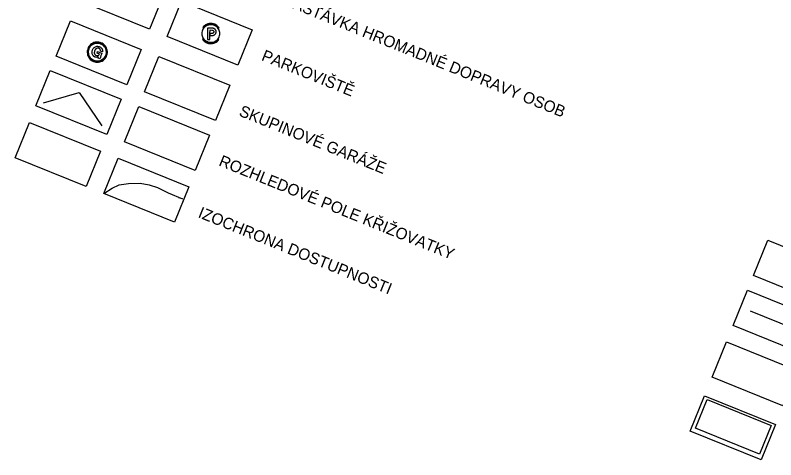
# Model space of a CAD drawing. Extents: x -522754 to -518969, y -1191121 to -1188171.
# Drawn here: x -521907 to -520911, y -1190701 to -1190119 of the extents above; entities that cross this region are included whole.
import ezdxf

# ---------------------------------------------------------------- set-up
doc = ezdxf.new("R2010")
doc.units = 0
for name, color, linetype in [('Implicitní', 7, 'Continuous'), ('ložisk_nerost', 7, 'Continuous'), ('odvodneni_s', 7, 'Continuous'), ('pe_prikop_s', 7, 'Continuous'), ('rozhled_pole_s', 7, 'Continuous')]:
    doc.layers.add(name, color=color, linetype=linetype)

msp = doc.modelspace()

# ---------------------------------------------------------------- linework, layer by layer
at = {"layer": 'Implicitní'}
for points in [[(-521804.94, -1190053.63), (-521712.26, -1190091.19), (-521731.04, -1190137.53), (-521823.72, -1190099.97)], [(-521689.09, -1190100.58), (-521596.41, -1190138.15), (-521615.19, -1190184.48), (-521707.87, -1190146.92)], [(-521834.39, -1190126.29), (-521741.71, -1190163.85), (-521760.49, -1190210.19), (-521853.17, -1190172.63)], [(-521718.54, -1190173.25), (-521625.86, -1190210.81), (-521644.64, -1190257.15), (-521737.32, -1190219.58)], [(-521860.85, -1190191.58), (-521768.17, -1190229.14), (-521786.95, -1190275.48), (-521879.63, -1190237.92)], [(-521745, -1190238.53), (-521652.32, -1190276.1), (-521671.1, -1190322.43), (-521763.78, -1190284.87)], [(-521887.96, -1190259.38), (-521795.28, -1190296.92), (-521814.05, -1190343.26), (-521906.73, -1190305.72)], [(-521772.11, -1190306.3), (-521679.42, -1190343.85), (-521698.19, -1190390.19), (-521790.88, -1190352.65)], [(-520921.74, -1190413.62), (-520829.06, -1190451.18), (-520847.84, -1190497.52), (-520940.52, -1190459.96)], [(-520948.23, -1190478.99), (-520855.55, -1190516.55), (-520874.33, -1190562.89), (-520967.01, -1190525.33)], [(-520975.71, -1190546.78), (-520883.03, -1190584.34), (-520901.81, -1190630.68), (-520994.49, -1190593.12)], [(-521004.31, -1190617.35), (-520911.63, -1190654.91), (-520930.41, -1190701.25), (-521023.09, -1190663.69)]]:
    msp.add_lwpolyline(points, close=True, dxfattribs=at)
msp.add_lwpolyline([(-521869.54, -1190233.73), (-521823.19, -1190220.35), (-521793.32, -1190263.89)], dxfattribs=at)
at = {"layer": 'ložisk_nerost'}
for points in [[(-521638.84, -1190143.37), (-521638.9, -1190141.86), (-521639.15, -1190140.38), (-521639.59, -1190138.95), (-521640.2, -1190137.57), (-521640.98, -1190136.29), (-521641.92, -1190135.12), (-521643, -1190134.07), (-521644.2, -1190133.17), (-521645.51, -1190132.42), (-521646.9, -1190131.85), (-521648.35, -1190131.46), (-521649.84, -1190131.25), (-521651.34, -1190131.24), (-521652.83, -1190131.41), (-521654.29, -1190131.77), (-521655.7, -1190132.31), (-521657.02, -1190133.03), (-521658.24, -1190133.9), (-521659.34, -1190134.92), (-521660.31, -1190136.08), (-521661.12, -1190137.34), (-521661.76, -1190138.7), (-521662.23, -1190140.13), (-521662.51, -1190141.6), (-521662.61, -1190143.1), (-521662.52, -1190144.6), (-521662.23, -1190146.08), (-521661.77, -1190147.51), (-521661.12, -1190148.87), (-521660.31, -1190150.13), (-521659.35, -1190151.29), (-521658.25, -1190152.31), (-521657.03, -1190153.19), (-521655.71, -1190153.9), (-521654.3, -1190154.45), (-521652.85, -1190154.81), (-521651.35, -1190154.98), (-521649.85, -1190154.97), (-521648.36, -1190154.76), (-521646.91, -1190154.37), (-521645.52, -1190153.8), (-521644.21, -1190153.06), (-521643.01, -1190152.16), (-521641.93, -1190151.11), (-521640.99, -1190149.94), (-521640.21, -1190148.65), (-521639.59, -1190147.28), (-521639.15, -1190145.85), (-521638.9, -1190144.36), (-521638.84, -1190143.37)], [(-521650.45, -1190129.9), (-521651.28, -1190129.91), (-521652.94, -1190130.09), (-521654.56, -1190130.47), (-521656.13, -1190131.05), (-521657.61, -1190131.83), (-521658.97, -1190132.79), (-521660.21, -1190133.91), (-521661.29, -1190135.18)], [(-521659.62, -1190135.21), (-521658.73, -1190134.31), (-521657.56, -1190133.37), (-521656.27, -1190132.59), (-521654.9, -1190131.98), (-521653.46, -1190131.54), (-521651.98, -1190131.29), (-521650.48, -1190131.22)], [(-521650.47, -1190131.22), (-521649.21, -1190131.32), (-521647.73, -1190131.61), (-521646.3, -1190132.08), (-521644.95, -1190132.72), (-521643.68, -1190133.54), (-521642.53, -1190134.5), (-521641.51, -1190135.61)], [(-521639.84, -1190135.64), (-521640.32, -1190134.98), (-521641.43, -1190133.73), (-521642.69, -1190132.63), (-521644.08, -1190131.7), (-521645.57, -1190130.95), (-521647.14, -1190130.4), (-521648.78, -1190130.05), (-521650.44, -1190129.9)], [(-521661.29, -1190135.18), (-521659.62, -1190135.21)], [(-521648.4, -1190136.03), (-521654.85, -1190135.89), (-521655.17, -1190150.78), (-521652, -1190150.85), (-521651.83, -1190142.99)], [(-521651.78, -1190142.99), (-521651.84, -1190145.57)], [(-521651.83, -1190142.99), (-521651.73, -1190138.42)], [(-521649.25, -1190143.05), (-521651.78, -1190142.99)], [(-521651.73, -1190138.42), (-521649.16, -1190138.48)], [(-521649.16, -1190138.48), (-521649.04, -1190138.48), (-521648.92, -1190138.48), (-521648.34, -1190138.61), (-521648.11, -1190138.74), (-521647.87, -1190138.86), (-521647.64, -1190138.98), (-521647.41, -1190139.22), (-521647.18, -1190139.46), (-521646.96, -1190139.81), (-521646.85, -1190140.17), (-521646.74, -1190140.76), (-521646.75, -1190140.99), (-521646.87, -1190141.46), (-521647, -1190141.81), (-521647.24, -1190142.15), (-521647.36, -1190142.27), (-521647.6, -1190142.5), (-521647.96, -1190142.73), (-521648.19, -1190142.84), (-521648.55, -1190142.95), (-521649.02, -1190143.05), (-521649.25, -1190143.05)], [(-521648.61, -1190145.64), (-521647.9, -1190145.54), (-521647.43, -1190145.43), (-521647.08, -1190145.33), (-521646.72, -1190145.21), (-521646.48, -1190145.1), (-521646.25, -1190144.99), (-521645.89, -1190144.76), (-521645.53, -1190144.54), (-521645.29, -1190144.31), (-521645.05, -1190144.08), (-521644.81, -1190143.85), (-521644.57, -1190143.5), (-521644.33, -1190143.16), (-521644.21, -1190142.92), (-521644.09, -1190142.69), (-521643.96, -1190142.34), (-521643.84, -1190141.99), (-521643.71, -1190141.41), (-521643.7, -1190141.06), (-521643.69, -1190140.59), (-521643.79, -1190140), (-521643.79, -1190139.88), (-521643.9, -1190139.53), (-521644.01, -1190139.18), (-521644.24, -1190138.7), (-521644.46, -1190138.35), (-521644.69, -1190137.99), (-521644.92, -1190137.75), (-521645.15, -1190137.51), (-521645.38, -1190137.27), (-521645.72, -1190137.03), (-521646.07, -1190136.79), (-521646.3, -1190136.66), (-521646.53, -1190136.54), (-521646.88, -1190136.42), (-521647.11, -1190136.29), (-521647.7, -1190136.16), (-521648.4, -1190136.03)], [(-521641.51, -1190135.61), (-521639.84, -1190135.64)], [(-521661.63, -1190150.57), (-521660.61, -1190151.88), (-521659.42, -1190153.06), (-521658.1, -1190154.07), (-521656.65, -1190154.92), (-521655.12, -1190155.57), (-521653.51, -1190156.02), (-521651.86, -1190156.27), (-521650.19, -1190156.31), (-521648.53, -1190156.13), (-521646.9, -1190155.75), (-521645.34, -1190155.17), (-521643.86, -1190154.39), (-521642.49, -1190153.43), (-521641.25, -1190152.31), (-521640.17, -1190151.04)], [(-521659.96, -1190150.61), (-521661.63, -1190150.57)], [(-521641.84, -1190151), (-521642.57, -1190151.75), (-521643.73, -1190152.71), (-521644.99, -1190153.52), (-521646.35, -1190154.16), (-521647.78, -1190154.63), (-521649.26, -1190154.91), (-521650.76, -1190155), (-521652.26, -1190154.9), (-521653.74, -1190154.61), (-521655.16, -1190154.14), (-521656.52, -1190153.49), (-521657.78, -1190152.68), (-521658.94, -1190151.71), (-521659.96, -1190150.61)], [(-521651.84, -1190145.57), (-521648.61, -1190145.64)], [(-521640.17, -1190151.04), (-521641.84, -1190151)], [(-521790.88, -1190352.65), (-521779.84, -1190345.61), (-521770.73, -1190341.03), (-521758.3, -1190339.3), (-521743.12, -1190339.05), (-521731.4, -1190341.17), (-521720.65, -1190344.53), (-521706.42, -1190351.6), (-521687.85, -1190359.41), (-521692.54, -1190358.08)]]:
    msp.add_lwpolyline(points, dxfattribs=at)
at = {"layer": 'odvodneni_s'}
msp.add_lwpolyline([(-521001.1, -1190622.49), (-520917.22, -1190656.49), (-520932.43, -1190694.02), (-521016.31, -1190660.03)], close=True, dxfattribs=at)
at = {"layer": 'pe_prikop_s'}
msp.add_line((-520944.8, -1190506.25), (-520870.66, -1190536.3), dxfattribs=at)
at = {"layer": 'rozhled_pole_s'}
for points in [[(-521794.49, -1190155.1), (-521795.53, -1190154.74), (-521797.16, -1190154.38), (-521798.82, -1190154.22), (-521800.49, -1190154.27), (-521802.14, -1190154.53), (-521803.75, -1190155), (-521805.28, -1190155.66), (-521806.71, -1190156.51), (-521808.03, -1190157.54), (-521809.2, -1190158.73), (-521810.22, -1190160.05), (-521811.06, -1190161.5), (-521811.72, -1190163.03), (-521812.17, -1190164.64), (-521812.42, -1190166.29), (-521812.45, -1190167.96), (-521812.28, -1190169.62), (-521811.9, -1190171.25), (-521811.31, -1190172.81), (-521810.54, -1190174.29), (-521809.58, -1190175.66), (-521808.46, -1190176.89), (-521807.19, -1190177.98), (-521805.79, -1190178.9), (-521804.29, -1190179.63), (-521802.71, -1190180.17), (-521801.07, -1190180.5), (-521799.41, -1190180.63), (-521797.74, -1190180.54), (-521796.1, -1190180.24), (-521794.51, -1190179.74), (-521792.99, -1190179.04), (-521791.57, -1190178.16), (-521790.28, -1190177.1), (-521789.13, -1190175.89), (-521788.14, -1190174.55), (-521787.33, -1190173.09), (-521786.71, -1190171.54), (-521786.29, -1190169.92), (-521786.08, -1190168.26), (-521786.07, -1190166.59), (-521786.28, -1190164.94), (-521786.7, -1190163.32), (-521787.32, -1190161.77), (-521788.13, -1190160.31), (-521789.11, -1190158.96), (-521790.26, -1190157.75), (-521791.55, -1190156.69), (-521792.97, -1190155.8), (-521794.48, -1190155.1)], [(-521794.96, -1190156.33), (-521794.05, -1190156.73), (-521792.75, -1190157.47), (-521791.54, -1190158.37), (-521790.46, -1190159.42), (-521789.52, -1190160.59), (-521788.74, -1190161.87), (-521788.13, -1190163.24), (-521787.69, -1190164.68), (-521787.43, -1190166.16), (-521787.37, -1190167.67), (-521787.5, -1190169.16), (-521787.81, -1190170.63), (-521788.31, -1190172.05), (-521788.98, -1190173.4), (-521789.82, -1190174.64), (-521790.8, -1190175.78), (-521791.93, -1190176.78), (-521793.17, -1190177.63), (-521794.5, -1190178.31), (-521795.92, -1190178.83), (-521797.38, -1190179.16), (-521798.88, -1190179.3), (-521800.38, -1190179.25), (-521801.87, -1190179.02), (-521803.31, -1190178.59), (-521804.69, -1190177.99), (-521805.98, -1190177.22), (-521807.16, -1190176.3), (-521808.22, -1190175.23), (-521809.13, -1190174.04), (-521809.89, -1190172.74), (-521810.47, -1190171.35), (-521810.88, -1190169.91), (-521811.1, -1190168.42), (-521811.14, -1190166.92), (-521810.98, -1190165.42), (-521810.63, -1190163.96), (-521810.1, -1190162.55), (-521809.4, -1190161.22), (-521808.54, -1190159.99), (-521807.53, -1190158.88), (-521806.39, -1190157.9), (-521805.13, -1190157.08), (-521803.78, -1190156.42), (-521802.35, -1190155.94), (-521800.88, -1190155.64), (-521799.38, -1190155.53), (-521797.88, -1190155.61), (-521796.4, -1190155.88), (-521794.97, -1190156.33)], [(-521788.17, -1190171.71), (-521787.72, -1190170.28), (-521787.45, -1190168.8), (-521787.37, -1190167.3), (-521787.48, -1190165.8), (-521787.78, -1190164.32), (-521788.26, -1190162.9), (-521788.92, -1190161.55), (-521789.74, -1190160.29), (-521790.72, -1190159.15), (-521791.83, -1190158.14), (-521793.06, -1190157.27), (-521794.39, -1190156.57), (-521795.79, -1190156.04), (-521797.26, -1190155.7), (-521798.75, -1190155.54), (-521800.25, -1190155.57), (-521801.74, -1190155.79), (-521803.19, -1190156.2), (-521804.57, -1190156.78), (-521805.87, -1190157.54), (-521807.06, -1190158.45), (-521808.13, -1190159.51), (-521809.06, -1190160.69), (-521809.83, -1190161.98), (-521810.43, -1190163.36), (-521810.85, -1190164.8), (-521811.09, -1190166.29), (-521811.14, -1190167.79), (-521811, -1190169.29), (-521810.67, -1190170.75), (-521810.16, -1190172.17), (-521809.47, -1190173.5), (-521808.62, -1190174.74), (-521807.62, -1190175.87), (-521806.49, -1190176.85), (-521805.24, -1190177.69), (-521803.9, -1190178.36), (-521802.48, -1190178.86), (-521801.01, -1190179.18), (-521799.51, -1190179.3), (-521798.01, -1190179.24), (-521796.53, -1190178.99), (-521795.09, -1190178.55), (-521793.72, -1190177.94), (-521792.43, -1190177.15), (-521791.26, -1190176.21), (-521790.21, -1190175.14), (-521789.31, -1190173.93), (-521788.57, -1190172.63), (-521788.17, -1190171.71)], [(-521805.54, -1190164.41), (-521804.51, -1190162.66)], [(-521804.51, -1190162.66), (-521804.1, -1190162.23)], [(-521804.1, -1190162.23), (-521803.65, -1190161.68)], [(-521803.65, -1190161.68), (-521803.14, -1190161.29)], [(-521803.14, -1190161.29), (-521802.77, -1190160.95)], [(-521802.77, -1190160.95), (-521802.44, -1190160.72)], [(-521802.44, -1190160.72), (-521800.86, -1190160.02)], [(-521800.79, -1190162.91), (-521801.3, -1190163.31)], [(-521800.86, -1190160.02), (-521799.69, -1190159.76)], [(-521800.28, -1190162.51), (-521800.79, -1190162.91)], [(-521799.56, -1190162.2), (-521800.28, -1190162.51)], [(-521799.69, -1190159.76), (-521799.44, -1190159.74)], [(-521799.31, -1190162.17), (-521799.56, -1190162.2)], [(-521799.44, -1190159.74), (-521798.84, -1190159.73)], [(-521798.92, -1190162.09), (-521799.31, -1190162.17)], [(-521798.32, -1190162.08), (-521798.92, -1190162.09)], [(-521798.84, -1190159.73), (-521797.94, -1190159.85)], [(-521797.87, -1190162.14), (-521798.32, -1190162.08)], [(-521797.94, -1190159.85), (-521796.86, -1190160.14)], [(-521797.04, -1190162.46), (-521797.87, -1190162.14)], [(-521796.56, -1190162.76), (-521797.04, -1190162.46)], [(-521796.86, -1190160.14), (-521796.03, -1190160.47)], [(-521796.29, -1190162.99), (-521796.56, -1190162.76)], [(-521796.02, -1190163.21), (-521796.29, -1190162.99)], [(-521796.03, -1190160.47), (-521795.24, -1190160.89)], [(-521795.62, -1190163.72), (-521796.02, -1190163.21)], [(-521795.24, -1190160.89), (-521794.77, -1190161.19)], [(-521794.97, -1190156.33), (-521794.49, -1190155.1)], [(-521794.48, -1190155.1), (-521794.96, -1190156.33)], [(-521794.77, -1190161.19), (-521794.49, -1190161.42)], [(-521794.49, -1190161.42), (-521794.22, -1190161.64)], [(-521794.22, -1190161.64), (-521793.89, -1190162.01)], [(-521793.89, -1190162.01), (-521793.49, -1190162.52)], [(-521793.49, -1190162.52), (-521793.2, -1190162.99)], [(-521793.2, -1190162.99), (-521793.07, -1190163.28)], [(-521806.18, -1190168.21), (-521806.13, -1190167.16)], [(-521806.15, -1190168.46), (-521806.18, -1190168.21)], [(-521806.13, -1190168.71), (-521806.15, -1190168.46)], [(-521806.13, -1190167.16), (-521806.01, -1190166.25)], [(-521806.04, -1190169.1), (-521806.13, -1190168.71)], [(-521805.93, -1190169.73), (-521806.04, -1190169.1)], [(-521806.01, -1190166.25), (-521805.92, -1190165.69)], [(-521805.17, -1190171.46), (-521805.93, -1190169.73)], [(-521805.92, -1190165.69), (-521805.78, -1190165.03)], [(-521805.78, -1190165.03), (-521805.54, -1190164.41)], [(-521804.77, -1190171.97), (-521805.17, -1190171.46)], [(-521804.54, -1190172.3), (-521804.77, -1190171.97)], [(-521804.38, -1190172.48), (-521804.54, -1190172.3)], [(-521804.11, -1190172.7), (-521804.38, -1190172.48)], [(-521803.94, -1190172.89), (-521804.11, -1190172.7)], [(-521803.56, -1190173.15), (-521803.94, -1190172.89)], [(-521803.29, -1190173.38), (-521803.56, -1190173.15)], [(-521803.17, -1190167.83), (-521803.23, -1190168.28)], [(-521803.23, -1190168.28), (-521803.01, -1190169.56)], [(-521803.15, -1190167.48), (-521803.17, -1190167.83)], [(-521803.04, -1190166.57), (-521803.15, -1190167.48)], [(-521802.8, -1190165.95), (-521803.04, -1190166.57)], [(-521803.01, -1190169.56), (-521802.94, -1190169.7)], [(-521802.94, -1190169.7), (-521802.81, -1190169.99)], [(-521802.81, -1190169.99), (-521802.69, -1190170.28)], [(-521802.32, -1190164.7), (-521802.8, -1190165.95)], [(-521802.69, -1190170.28), (-521802.52, -1190170.46)], [(-521802.52, -1190170.46), (-521802.29, -1190170.79)], [(-521802.05, -1190164.33), (-521802.32, -1190164.7)], [(-521802.29, -1190170.79), (-521801.85, -1190171.19)], [(-521801.79, -1190163.95), (-521802.05, -1190164.33)], [(-521801.85, -1190171.19), (-521801.48, -1190171.46)], [(-521801.56, -1190163.68), (-521801.79, -1190163.95)], [(-521801.3, -1190163.31), (-521801.56, -1190163.68)], [(-521801.48, -1190171.46), (-521800.75, -1190171.74)], [(-521800.75, -1190171.74), (-521800.09, -1190171.88)], [(-521800.09, -1190171.88), (-521799.64, -1190171.93)], [(-521799.64, -1190171.93), (-521799.14, -1190171.89)], [(-521799.63, -1190168.84), (-521798.83, -1190166.77)], [(-521796.42, -1190170.08), (-521799.63, -1190168.84)], [(-521799.14, -1190171.89), (-521798.5, -1190171.77)], [(-521798.83, -1190166.77), (-521795.83, -1190167.93)], [(-521798.5, -1190171.77), (-521798.36, -1190171.71)], [(-521798.36, -1190171.71), (-521797.79, -1190171.46)], [(-521797.79, -1190171.46), (-521797.46, -1190171.23)], [(-521797.46, -1190171.23), (-521796.91, -1190170.73)], [(-521796.91, -1190170.73), (-521796.68, -1190170.46)], [(-521796.68, -1190170.46), (-521796.42, -1190170.08)], [(-521795.83, -1190167.93), (-521793.24, -1190168.93)], [(-521795.43, -1190164.15), (-521795.62, -1190163.72)], [(-521795.37, -1190164.3), (-521795.43, -1190164.15)], [(-521795.22, -1190164.83), (-521795.37, -1190164.3)], [(-521795.17, -1190165.32), (-521795.22, -1190164.83)], [(-521795.21, -1190166.03), (-521795.17, -1190165.32)], [(-521792.58, -1190166.92), (-521795.21, -1190166.03)], [(-521794.44, -1190172.04), (-521795.16, -1190173.91)], [(-521793.76, -1190170.28), (-521794.44, -1190172.04)], [(-521793.24, -1190168.93), (-521793.76, -1190170.28)], [(-521793.07, -1190163.28), (-521792.82, -1190163.85)], [(-521792.82, -1190163.85), (-521792.67, -1190164.39)], [(-521792.67, -1190164.39), (-521792.58, -1190164.78)], [(-521792.58, -1190164.78), (-521792.45, -1190165.67)], [(-521792.48, -1190166.37), (-521792.58, -1190166.92)], [(-521792.46, -1190166.02), (-521792.48, -1190166.37)], [(-521792.45, -1190165.67), (-521792.46, -1190166.02)], [(-521802.61, -1190173.76), (-521803.29, -1190173.38)], [(-521801.88, -1190174.04), (-521802.61, -1190173.76)], [(-521801.22, -1190174.18), (-521801.88, -1190174.04)], [(-521800.31, -1190174.29), (-521801.22, -1190174.18)], [(-521799.57, -1190174.22), (-521800.31, -1190174.29)], [(-521799.18, -1190174.14), (-521799.57, -1190174.22)], [(-521798.64, -1190173.99), (-521799.18, -1190174.14)], [(-521798.22, -1190173.79), (-521798.64, -1190173.99)], [(-521797.6, -1190173.44), (-521798.22, -1190173.79)], [(-521798.14, -1190175.14), (-521797.6, -1190173.44)], [(-521795.96, -1190175.98), (-521798.14, -1190175.14)], [(-521795.16, -1190173.91), (-521795.96, -1190175.98)]]:
    msp.add_lwpolyline(points, dxfattribs=at)

# ---------------------------------------------------------------- texts
at = {"layer": 'Implicitní'}
for s, rotation, p in [('ZASTÁVKA HROMADNÉ DOPRAVY OSOB', 337.93793, (-521556, -1190105)), ('PARKOVIŠTĚ', 337.93793, (-521585.45, -1190177.66)), ('SKUPINOVÉ GARÁŽE', 337.93793, (-521614.9, -1190250.32)), ('ROZHLEDOVÉ POLE KŘIŽOVATKY', 337.93793, (-521641.36, -1190315.61)), ('IZOCHRONA DOSTUPNOSTI', 337.94866, (-521668.45, -1190383.36))]:
    msp.add_text(s, height=15, rotation=rotation, dxfattribs=at).set_placement(p)

doc.saveas('drawing.dxf')
